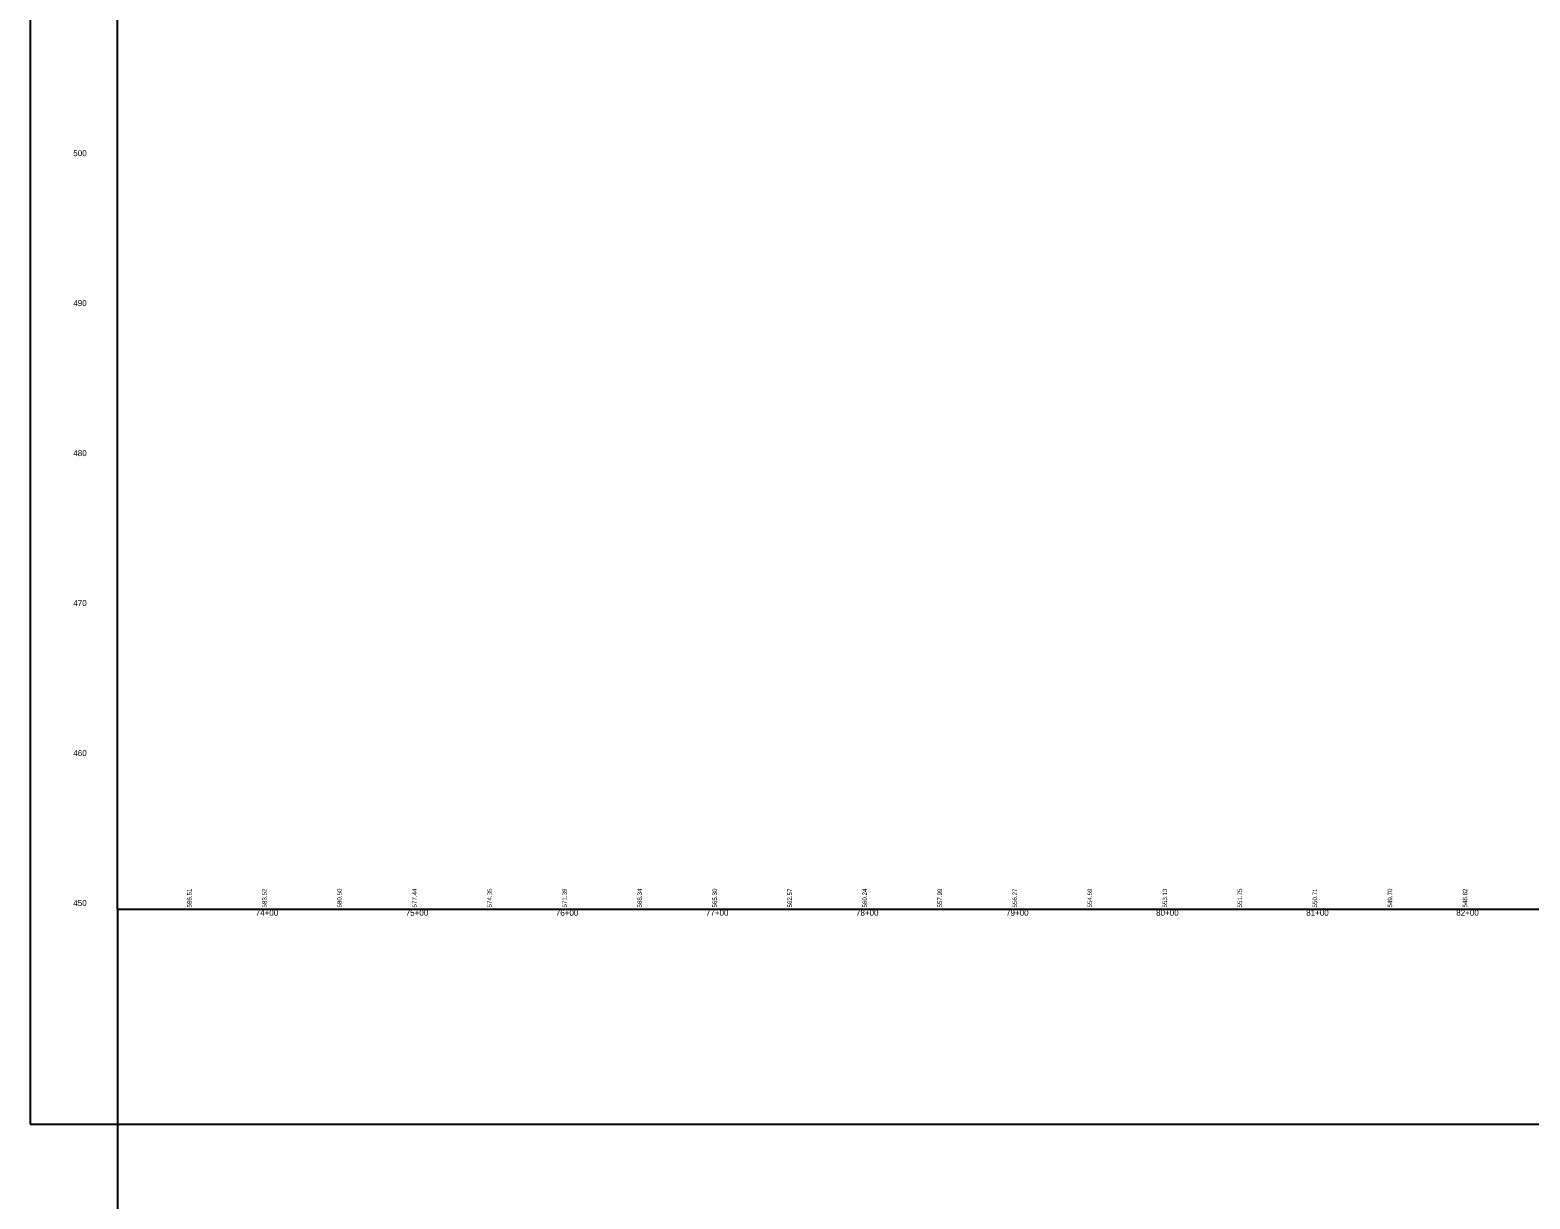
# Model space of a CAD drawing. Extents: x 1733822 to 1737718, y 1214897 to 1219897.
# Drawn here: x 1733822 to 1734821, y 1217203 to 1217983 of the extents above; entities that cross this region are included whole.
import ezdxf

# ---------------------------------------------------------------- set-up
doc = ezdxf.new("R2010")
doc.units = 0
for name, color, linetype in [('Default', 7, 'Continuous'), ('RD_DDB_ElevTX', 7, 'Continuous'), ('RD_DDB_StaTX', 7, 'Continuous'), ('RD_DDB_StripGrade', 7, 'Continuous'), ('RD_Sketch8', 7, 'Continuous')]:
    doc.layers.add(name, color=color, linetype=linetype)

msp = doc.modelspace()

# ---------------------------------------------------------------- linework, layer by layer
at = {"layer": 'Default'}
for q in [(1733879.77, 1219896.76), (1737279.77, 1217396.76), (1733879.77, 1214896.76)]:
    msp.add_line((1733879.77, 1217396.76), q, dxfattribs=at)
at = {"layer": 'RD_Sketch8'}
msp.add_lwpolyline([(1733821.56, 1217253.41), (1737421.56, 1217253.41), (1737421.56, 1219453.41), (1733821.56, 1219453.41)], close=True, dxfattribs=at)

# ---------------------------------------------------------------- texts
at = {"layer": 'Default'}
for s, p in [('138', (1733879.77, 1217396.83)), ('S138', (1733879.77, 1217396.82)), ('7300.000000', (1733879.77, 1217396.81)), ('450', (1733879.77, 1217396.8)), ('100', (1733879.77, 1217396.79)), ('10', (1733879.77, 1217396.78)), ('NOGAP', (1733879.77, 1217396.77))]:
    msp.add_text(s, height=0.00975, dxfattribs=at).set_placement(p)
at = {"layer": 'RD_DDB_ElevTX'}
for s, p in [('500', (1733850.4, 1217898.76)), ('500', (1733850.4, 1217898.76)), ('500', (1733850.4, 1217898.76)), ('500', (1733850.4, 1217898.76)), ('500', (1733850.4, 1217898.76)), ('490', (1733850.4, 1217798.76)), ('490', (1733850.4, 1217798.76)), ('490', (1733850.4, 1217798.76)), ('490', (1733850.4, 1217798.76)), ('490', (1733850.4, 1217798.76)), ('480', (1733850.4, 1217698.76)), ('480', (1733850.4, 1217698.76)), ('480', (1733850.4, 1217698.76)), ('480', (1733850.4, 1217698.76)), ('480', (1733850.4, 1217698.76)), ('470', (1733850.4, 1217598.76)), ('470', (1733850.4, 1217598.76)), ('470', (1733850.4, 1217598.76)), ('470', (1733850.4, 1217598.76)), ('470', (1733850.4, 1217598.76)), ('460', (1733850.4, 1217498.76)), ('460', (1733850.4, 1217498.76)), ('460', (1733850.4, 1217498.76)), ('460', (1733850.4, 1217498.76)), ('460', (1733850.4, 1217498.76)), ('450', (1733850.4, 1217398.76)), ('450', (1733850.4, 1217398.76)), ('450', (1733850.4, 1217398.76)), ('450', (1733850.4, 1217398.76)), ('450', (1733850.4, 1217398.76))]:
    msp.add_text(s, height=4, dxfattribs=at).set_placement(p)
at = {"layer": 'RD_DDB_StaTX'}
for s, p in [('74+00', (1733971.95, 1217392.26)), ('74+00', (1733971.95, 1217392.26)), ('74+00', (1733971.95, 1217392.26)), ('74+00', (1733971.95, 1217392.26)), ('74+00', (1733971.95, 1217392.26)), ('75+00', (1734071.95, 1217392.26)), ('75+00', (1734071.95, 1217392.26)), ('75+00', (1734071.95, 1217392.26)), ('75+00', (1734071.95, 1217392.26)), ('75+00', (1734071.95, 1217392.26)), ('76+00', (1734171.95, 1217392.26)), ('76+00', (1734171.95, 1217392.26)), ('76+00', (1734171.95, 1217392.26)), ('76+00', (1734171.95, 1217392.26)), ('76+00', (1734171.95, 1217392.26)), ('77+00', (1734271.95, 1217392.26)), ('77+00', (1734271.95, 1217392.26)), ('77+00', (1734271.95, 1217392.26)), ('77+00', (1734271.95, 1217392.26)), ('77+00', (1734271.95, 1217392.26)), ('78+00', (1734371.95, 1217392.26)), ('78+00', (1734371.95, 1217392.26)), ('78+00', (1734371.95, 1217392.26)), ('78+00', (1734371.95, 1217392.26)), ('78+00', (1734371.95, 1217392.26)), ('79+00', (1734471.95, 1217392.26)), ('79+00', (1734471.95, 1217392.26)), ('79+00', (1734471.95, 1217392.26)), ('79+00', (1734471.95, 1217392.26)), ('79+00', (1734471.95, 1217392.26)), ('80+00', (1734571.95, 1217392.26)), ('80+00', (1734571.95, 1217392.26)), ('80+00', (1734571.95, 1217392.26)), ('80+00', (1734571.95, 1217392.26)), ('80+00', (1734571.95, 1217392.26)), ('81+00', (1734671.95, 1217392.26)), ('81+00', (1734671.95, 1217392.26)), ('81+00', (1734671.95, 1217392.26)), ('81+00', (1734671.95, 1217392.26)), ('81+00', (1734671.95, 1217392.26)), ('82+00', (1734771.95, 1217392.26)), ('82+00', (1734771.95, 1217392.26)), ('82+00', (1734771.95, 1217392.26)), ('82+00', (1734771.95, 1217392.26)), ('82+00', (1734771.95, 1217392.26))]:
    msp.add_text(s, height=4, dxfattribs=at).set_placement(p)
at = {"layer": 'RD_DDB_StripGrade'}
for s, p in [('586.51', (1733929.27, 1217397.76)), ('583.52', (1733979.27, 1217397.76)), ('580.50', (1734029.27, 1217397.76)), ('577.44', (1734079.27, 1217397.76)), ('574.35', (1734129.27, 1217397.76)), ('571.39', (1734179.27, 1217397.76)), ('568.34', (1734229.27, 1217397.76)), ('565.30', (1734279.27, 1217397.76)), ('562.57', (1734329.27, 1217397.76)), ('560.24', (1734379.27, 1217397.76)), ('557.99', (1734429.27, 1217397.76)), ('556.27', (1734479.27, 1217397.76)), ('554.59', (1734529.27, 1217397.76)), ('553.13', (1734579.27, 1217397.76)), ('551.75', (1734629.27, 1217397.76)), ('550.71', (1734679.27, 1217397.76)), ('549.70', (1734729.27, 1217397.76)), ('548.82', (1734779.27, 1217397.76))]:
    msp.add_text(s, height=3, rotation=90, dxfattribs=at).set_placement(p)

doc.saveas('drawing.dxf')
